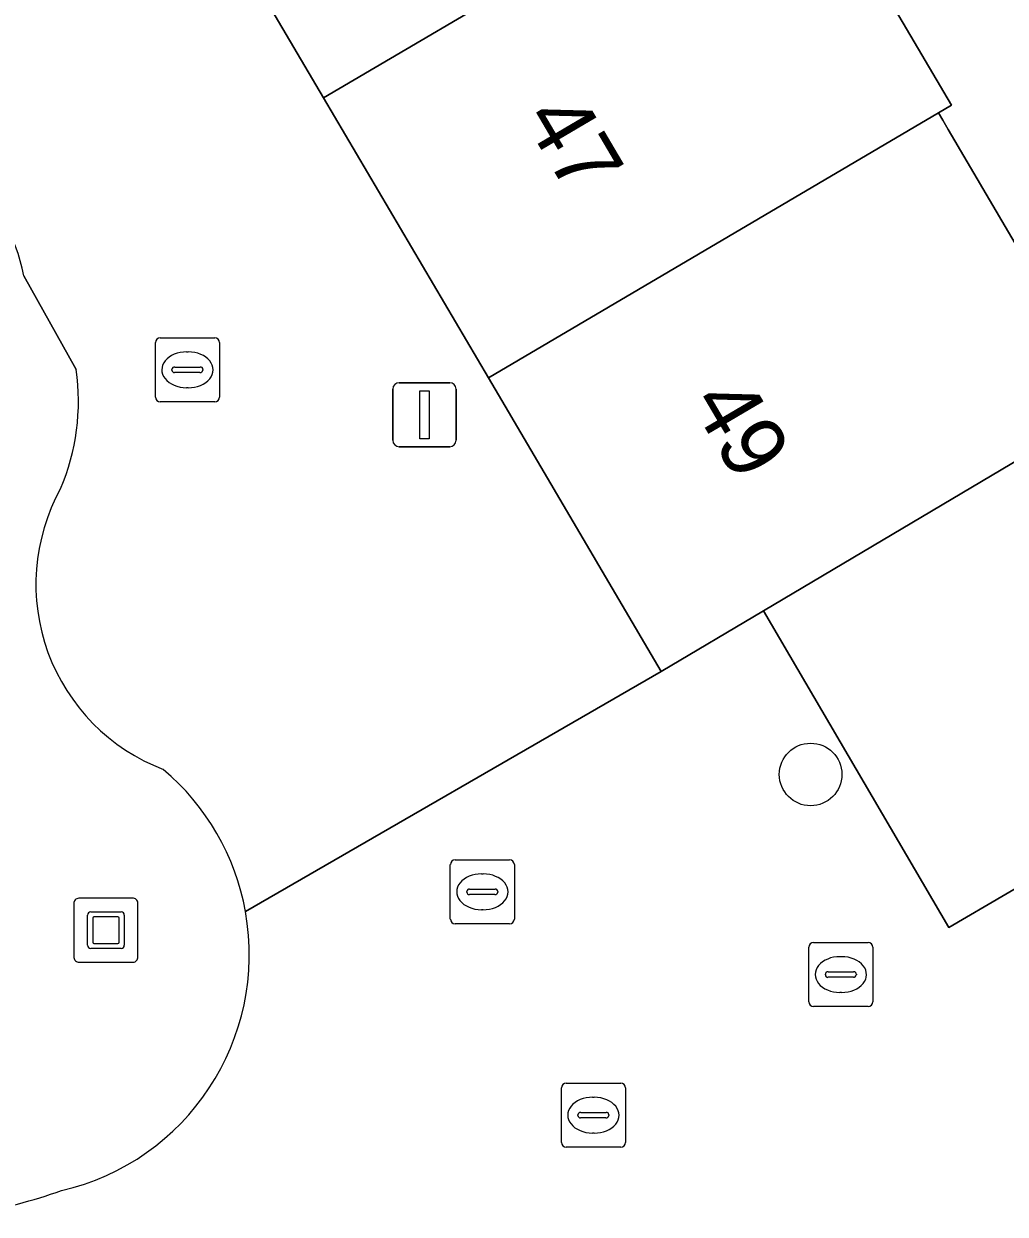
# Model space of a CAD drawing. Extents: x 161771 to 163125, y 382475 to 383179.
# Drawn here: x 162219.32 to 162234.66, y 382801.66 to 382820.27 of the extents above; entities that cross this region are included whole.
import ezdxf

# ---------------------------------------------------------------- set-up
doc = ezdxf.new("R2010")
doc.units = 0
for name, color, linetype in [('IMGEO_Boom', 7, 'Continuous'), ('IMGEO_Erf', 7, 'Continuous'), ('IMGEO_Groenvoorziening', 7, 'Continuous'), ('IMGEO_Kolk', 7, 'Continuous'), ('IMGEO_Kunstobject', 7, 'Continuous'), ('IMGEO_Lichtmast', 7, 'Continuous'), ('IMGEO_Pand', 7, 'Continuous'), ('IMGEO_Pand_nummerreeks', 7, 'Continuous'), ('IMGEO_Parkeervlak_open', 7, 'Continuous'), ('IMGEO_Rioolput', 7, 'Continuous'), ('IMGEO_Woonerf_open', 7, 'Continuous')]:
    doc.layers.add(name, color=color, linetype=linetype)

msp = doc.modelspace()

# ---------------------------------------------------------------- linework, layer by layer
at = {"layer": 'IMGEO_Boom'}
msp.add_circle((162231.621, 382808.538), 0.489, dxfattribs=at)
at = {"layer": 'IMGEO_Erf'}
msp.add_lwpolyline([(162238.913, 382831.272), (162232.428, 382841.879), (162229.308, 382840.042), (162227.749, 382839.124), (162227.869, 382838.92), (162228.972, 382837.044), (162224.377, 382834.343), (162225.271, 382832.823), (162225.586, 382833.009), (162226.104, 382832.128), (162228.677, 382827.751), (162231.249, 382823.375), (162233.822, 382818.999), (162233.619, 382818.879), (162233.686, 382818.765), (162233.77, 382818.622), (162236.304, 382814.311)], dxfattribs=at)
at = {"layer": 'IMGEO_Groenvoorziening'}
msp.add_lwpolyline([(162220.141, 382814.867), (162219.322, 382816.333)], dxfattribs=at)
for centre, radius, start, end in [((162216.544, 382815.808), 2.827, 10.7095, 161.7069), ((162216.669, 382814.377), 3.507, 336.9758, 8.0245), ((162222.607, 382811.51), 3.096, 151.1064, 249.1133), ((162219.06, 382805.723), 3.787, 10.2164, 49.8272), ((162219.059, 382805.724), 3.788, 282.9858, 10.1997), ((162216.798, 382810.916), 9.412, 280.5915, 289.3074)]:
    msp.add_arc(centre, radius, start, end, dxfattribs=at)
at = {"layer": 'IMGEO_Kolk'}
for p, q in [((162221.379, 382814.438), (162221.379, 382815.29)), ((162221.454, 382815.364), (162222.306, 382815.364)), ((162222.38, 382815.29), (162222.38, 382814.438)), ((162221.867, 382815.144), (162221.892, 382815.144)), ((162221.638, 382814.858), (162221.638, 382814.87)), ((162221.681, 382814.907), (162222.079, 382814.907)), ((162222.122, 382814.87), (162222.122, 382814.858)), ((162222.076, 382814.821), (162221.678, 382814.821)), ((162221.89, 382814.584), (162221.865, 382814.584)), ((162222.306, 382814.364), (162221.454, 382814.364)), ((162225.989, 382806.278), (162225.989, 382807.13)), ((162226.064, 382807.204), (162226.916, 382807.204)), ((162226.99, 382807.13), (162226.99, 382806.278)), ((162226.477, 382806.984), (162226.502, 382806.984)), ((162226.248, 382806.698), (162226.248, 382806.71)), ((162226.291, 382806.747), (162226.689, 382806.747)), ((162226.732, 382806.71), (162226.732, 382806.698)), ((162226.686, 382806.661), (162226.288, 382806.661)), ((162226.5, 382806.424), (162226.475, 382806.424)), ((162226.916, 382806.204), (162226.064, 382806.204)), ((162231.593, 382804.984), (162231.593, 382805.836)), ((162231.668, 382805.91), (162232.52, 382805.91)), ((162232.594, 382805.836), (162232.594, 382804.984)), ((162232.081, 382805.69), (162232.106, 382805.69)), ((162231.852, 382805.404), (162231.852, 382805.416)), ((162231.895, 382805.453), (162232.293, 382805.453)), ((162232.336, 382805.416), (162232.336, 382805.404)), ((162232.29, 382805.367), (162231.892, 382805.367)), ((162232.104, 382805.13), (162232.079, 382805.13)), ((162232.52, 382804.91), (162231.668, 382804.91))]:
    msp.add_line(p, q, dxfattribs=at)
for points in [[(162221.379, 382814.438), (162221.379, 382815.29)], [(162221.454, 382815.364), (162222.306, 382815.364)], [(162222.38, 382815.29), (162222.38, 382814.438)], [(162222.306, 382814.364), (162221.454, 382814.364)], [(162225.989, 382806.278), (162225.989, 382807.13)], [(162226.064, 382807.204), (162226.916, 382807.204)], [(162226.99, 382807.13), (162226.99, 382806.278)], [(162226.916, 382806.204), (162226.064, 382806.204)], [(162231.593, 382804.984), (162231.593, 382805.836)], [(162231.668, 382805.91), (162232.52, 382805.91)], [(162232.594, 382805.836), (162232.594, 382804.984)], [(162232.52, 382804.91), (162231.668, 382804.91)]]:
    msp.add_lwpolyline(points, dxfattribs=at)
for centre, radius, start, end in [((162221.456, 382815.288), 0.0765, 91.552, 178.448), ((162221.456, 382815.288), 0.0765, 91.552, 178.448), ((162222.304, 382815.288), 0.0765, 1.552, 88.448), ((162222.304, 382815.288), 0.0765, 1.552, 88.448), ((162221.678, 382814.867), 0.0403, 85.8775, 175.7526), ((162222.083, 382814.869), 0.0386, 1.7309, 96.639), ((162221.675, 382814.857), 0.0366, 178.938, 274.7102), ((162222.079, 382814.864), 0.043, 264.8664, 352.4533), ((162221.456, 382814.44), 0.0765, 181.552, 268.448), ((162221.456, 382814.44), 0.0765, 181.552, 268.448), ((162222.304, 382814.44), 0.0765, 271.552, 358.448), ((162222.304, 382814.44), 0.0765, 271.552, 358.448), ((162226.066, 382807.128), 0.0765, 91.552, 178.448), ((162226.066, 382807.128), 0.0765, 91.552, 178.448), ((162226.914, 382807.128), 0.0765, 1.552, 88.448), ((162226.914, 382807.128), 0.0765, 1.552, 88.448), ((162226.288, 382806.707), 0.0403, 85.8775, 175.7526), ((162226.285, 382806.697), 0.0366, 178.938, 274.7102), ((162226.689, 382806.704), 0.043, 264.8664, 352.4533), ((162226.693, 382806.709), 0.0386, 1.7309, 96.639), ((162226.066, 382806.28), 0.0765, 181.552, 268.448), ((162226.066, 382806.28), 0.0765, 181.552, 268.448), ((162226.914, 382806.28), 0.0765, 271.552, 358.448), ((162226.914, 382806.28), 0.0765, 271.552, 358.448), ((162231.67, 382805.834), 0.0765, 91.552, 178.448), ((162231.67, 382805.834), 0.0765, 91.552, 178.448), ((162232.518, 382805.834), 0.0765, 1.552, 88.448), ((162232.518, 382805.834), 0.0765, 1.552, 88.448), ((162231.892, 382805.413), 0.0403, 85.8775, 175.7526), ((162231.889, 382805.403), 0.0366, 178.938, 274.7102), ((162232.293, 382805.41), 0.043, 264.8664, 352.4533), ((162232.297, 382805.415), 0.0386, 1.7309, 96.639), ((162231.67, 382804.986), 0.0765, 181.552, 268.448), ((162231.67, 382804.986), 0.0765, 181.552, 268.448), ((162232.518, 382804.986), 0.0765, 271.552, 358.448), ((162232.518, 382804.986), 0.0765, 271.552, 358.448)]:
    msp.add_arc(centre, radius, start, end, dxfattribs=at)
for centre, major_axis, ratio, start_param, end_param in [((162221.866, 382814.864), (-0.387, 0.002), 0.722429, 4.712389, 7.853982), ((162221.891, 382814.864), (-0.39, 0.002), 0.717154, 1.570796, 4.712389), ((162226.476, 382806.704), (-0.387, 0.002), 0.722429, 4.712389, 7.853982), ((162226.501, 382806.704), (-0.39, 0.002), 0.717154, 1.570796, 4.712389), ((162232.08, 382805.41), (-0.387, 0.002), 0.722429, 4.712389, 7.853982), ((162232.105, 382805.41), (-0.39, 0.002), 0.717154, 1.570796, 4.712389)]:
    msp.add_ellipse(centre, major_axis=major_axis, ratio=ratio, start_param=start_param, end_param=end_param, dxfattribs=at)
at = {"layer": 'IMGEO_Kunstobject'}
for p, q in [((162220.105, 382806.519), (162220.105, 382805.678)), ((162220.105, 382806.519), (162220.105, 382805.678)), ((162221.021, 382806.603), (162220.18, 382806.603)), ((162221.021, 382806.603), (162220.18, 382806.603)), ((162221.105, 382805.687), (162221.105, 382806.528)), ((162221.105, 382805.687), (162221.105, 382806.528)), ((162220.319, 382805.867), (162220.319, 382806.341)), ((162220.369, 382806.391), (162220.843, 382806.391)), ((162220.793, 382806.311), (162220.419, 382806.311)), ((162220.893, 382806.341), (162220.893, 382805.867)), ((162220.399, 382806.291), (162220.399, 382805.917)), ((162220.813, 382805.917), (162220.813, 382806.291)), ((162220.843, 382805.817), (162220.369, 382805.817)), ((162220.419, 382805.897), (162220.793, 382805.897)), ((162220.189, 382805.603), (162221.03, 382805.603)), ((162220.189, 382805.603), (162221.03, 382805.603))]:
    msp.add_line(p, q, dxfattribs=at)
for centre, radius, start, end in [((162220.183, 382806.525), 0.0779, 92.4484, 184.2845), ((162220.183, 382806.525), 0.0779, 92.4484, 184.2845), ((162221.027, 382806.525), 0.0779, 2.4484, 94.2845), ((162221.027, 382806.525), 0.0779, 2.4484, 94.2845), ((162220.369, 382806.341), 0.05, 90, 180), ((162220.419, 382806.291), 0.02, 90, 180), ((162220.793, 382806.291), 0.02, 360, 90), ((162220.843, 382806.341), 0.05, 360, 90), ((162220.369, 382805.867), 0.05, 180, 270), ((162220.419, 382805.917), 0.02, 180, 270), ((162220.793, 382805.917), 0.02, 270, 0), ((162220.843, 382805.867), 0.05, 270, 0), ((162220.183, 382805.681), 0.0779, 182.4484, 274.2845), ((162220.183, 382805.681), 0.0779, 182.4484, 274.2845), ((162221.027, 382805.681), 0.0779, 272.4484, 4.2845), ((162221.027, 382805.681), 0.0779, 272.4484, 4.2845)]:
    msp.add_arc(centre, radius, start, end, dxfattribs=at)
at = {"layer": 'IMGEO_Lichtmast'}
for p, q in [((162225.09, 382813.762), (162225.09, 382814.562)), ((162225.09, 382814.562), (162225.09, 382813.762)), ((162225.19, 382814.662), (162225.98, 382814.662)), ((162225.98, 382814.662), (162225.19, 382814.662)), ((162226.08, 382814.562), (162226.08, 382813.762)), ((162226.08, 382813.762), (162226.08, 382814.562)), ((162225.98, 382813.662), (162225.19, 382813.662)), ((162225.19, 382813.662), (162225.98, 382813.662))]:
    msp.add_line(p, q, dxfattribs=at)
msp.add_lwpolyline([(162225.51, 382814.537), (162225.66, 382814.537), (162225.66, 382813.787), (162225.51, 382813.787), (162225.51, 382814.537)], dxfattribs=at)
for centre, start, end in [((162225.19, 382814.562), 90, 180), ((162225.19, 382814.562), 90, 180), ((162225.98, 382814.562), 0, 90), ((162225.98, 382814.562), 360, 90), ((162225.19, 382813.762), 180, 270), ((162225.19, 382813.762), 180, 270), ((162225.98, 382813.762), 270, 0), ((162225.98, 382813.762), 270, 0)]:
    msp.add_arc(centre, 0.1, start, end, dxfattribs=at)
at = {"layer": 'IMGEO_Pand'}
for points in [[(162228.677, 382827.751), (162221.434, 382823.487), (162224.009, 382819.113), (162231.249, 382823.375)], [(162231.249, 382823.375), (162224.009, 382819.113), (162226.584, 382814.737), (162233.619, 382818.879), (162233.822, 382818.999)], [(162233.77, 382818.622), (162233.686, 382818.765), (162233.619, 382818.879), (162226.584, 382814.737), (162229.285, 382810.148), (162230.884, 382811.096), (162236.304, 382814.311)]]:
    msp.add_lwpolyline(points, close=True, dxfattribs=at)
at = {"layer": 'IMGEO_Parkeervlak_open'}
msp.add_lwpolyline([(162238.887, 382815.82), (162236.304, 382814.311), (162230.884, 382811.096), (162233.78, 382806.145), (162241.801, 382810.837)], close=True, dxfattribs=at)
at = {"layer": 'IMGEO_Rioolput'}
for p, q in [((162227.8, 382803.712), (162228.652, 382803.712)), ((162227.725, 382802.786), (162227.725, 382803.638)), ((162228.726, 382803.638), (162228.726, 382802.786)), ((162228.213, 382803.492), (162228.238, 382803.492)), ((162227.984, 382803.206), (162227.984, 382803.218)), ((162228.422, 382803.169), (162228.024, 382803.169)), ((162228.027, 382803.255), (162228.425, 382803.255)), ((162228.468, 382803.218), (162228.468, 382803.206)), ((162228.236, 382802.932), (162228.211, 382802.932)), ((162228.652, 382802.712), (162227.8, 382802.712))]:
    msp.add_line(p, q, dxfattribs=at)
for points in [[(162227.8, 382803.712), (162228.652, 382803.712)], [(162227.725, 382802.786), (162227.725, 382803.638)], [(162228.726, 382803.638), (162228.726, 382802.786)], [(162228.652, 382802.712), (162227.8, 382802.712)]]:
    msp.add_lwpolyline(points, dxfattribs=at)
for centre, radius, start, end in [((162227.802, 382803.636), 0.0765, 91.552, 178.448), ((162227.802, 382803.636), 0.0765, 91.552, 178.448), ((162228.65, 382803.636), 0.0765, 1.552, 88.448), ((162228.65, 382803.636), 0.0765, 1.552, 88.448), ((162228.024, 382803.215), 0.0403, 85.8775, 175.7526), ((162228.021, 382803.205), 0.0366, 178.938, 274.7102), ((162228.425, 382803.212), 0.043, 264.8664, 352.4533), ((162228.429, 382803.217), 0.0386, 1.7309, 96.639), ((162227.802, 382802.788), 0.0765, 181.552, 268.448), ((162227.802, 382802.788), 0.0765, 181.552, 268.448), ((162228.65, 382802.788), 0.0765, 271.552, 358.448), ((162228.65, 382802.788), 0.0765, 271.552, 358.448)]:
    msp.add_arc(centre, radius, start, end, dxfattribs=at)
for centre, major_axis, ratio, start_param, end_param in [((162228.212, 382803.212), (-0.387, 0.002), 0.722429, 4.712389, 7.853982), ((162228.237, 382803.212), (-0.39, 0.002), 0.717154, 1.570796, 4.712389)]:
    msp.add_ellipse(centre, major_axis=major_axis, ratio=ratio, start_param=start_param, end_param=end_param, dxfattribs=at)
at = {"layer": 'IMGEO_Woonerf_open'}
for points in [[(162222.787, 382806.395), (162229.285, 382810.148), (162226.584, 382814.737), (162224.009, 382819.113), (162221.434, 382823.487), (162218.859, 382827.862), (162216.223, 382832.34), (162213.983, 382836.145), (162211.658, 382840.097), (162209.393, 382843.944), (162207.129, 382847.791), (162204.864, 382851.639), (162202.6, 382855.486), (162200.335, 382859.333)], [(162284.383, 382842.553), (162283.477, 382842.022), (162279.427, 382839.641), (162275.547, 382837.361), (162271.667, 382835.081), (162267.788, 382832.801), (162263.908, 382830.52), (162260.009, 382828.229), (162256.216, 382825.999), (162252.42, 382823.768), (162248.564, 382821.502), (162245.808, 382819.868), (162238.887, 382815.82), (162241.801, 382810.837), (162233.78, 382806.145), (162230.884, 382811.096), (162229.285, 382810.148), (162222.787, 382806.395)], [(162219.322, 382816.333), (162220.141, 382814.867)]]:
    msp.add_lwpolyline(points, dxfattribs=at)
for centre, radius, start, end in [((162216.544, 382815.808), 2.827, 10.7095, 161.7069), ((162216.669, 382814.377), 3.507, 336.9758, 8.0245), ((162222.607, 382811.51), 3.096, 151.1064, 249.1133), ((162219.06, 382805.723), 3.787, 10.2164, 49.8272), ((162219.059, 382805.724), 3.788, 282.9858, 10.1997), ((162216.798, 382810.916), 9.412, 280.5915, 289.3074)]:
    msp.add_arc(centre, radius, start, end, dxfattribs=at)

# ---------------------------------------------------------------- texts
at = {"layer": 'IMGEO_Pand_nummerreeks'}
for s, p in [('47', (162227.119, 382818.797)), ('49', (162229.731, 382814.358))]:
    msp.add_text(s, height=1, rotation=300.4811, dxfattribs=at).set_placement(p)

doc.saveas('drawing.dxf')
